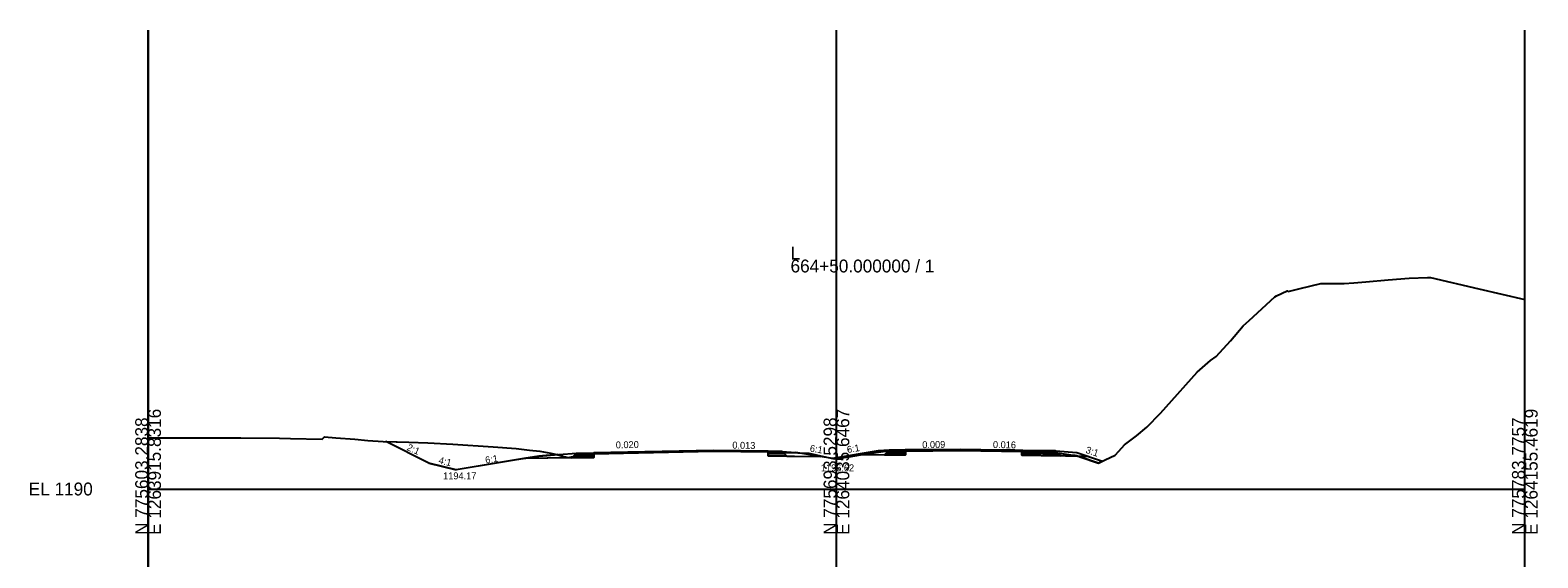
# Model space of a CAD drawing. Extents: x -41 to 1262860, y -100 to 777489.
# Drawn here: x -25.7 to 302.8, y 965 to 1080 of the extents above; entities that cross this region are included whole.
import ezdxf

# ---------------------------------------------------------------- set-up
doc = ezdxf.new("R2010")
doc.units = 0
for name, color, linetype in [('Exist Cross Section Cell', 7, 'Continuous'), ('Exist XS Center Line Elevation Label', 7, 'Continuous'), ('Exist XS Ground Line', 7, 'Continuous'), ('Prop CMT Pvmt Course 1', 7, 'Continuous'), ('Prop CMT Pvmt Surface', 7, 'Continuous'), ('Prop CMT Shld Paved Course 1', 7, 'Continuous'), ('Prop CMT Shld Paved Course 2', 7, 'Continuous'), ('Prop CMT Shld Paved Course 4', 7, 'Continuous'), ('Prop CMT Subgrade Earthwork', 7, 'Continuous'), ('Prop XS Ditch Standard Text', 7, 'Continuous'), ('Prop XS Earthwork Shape', 7, 'Continuous'), ('Prop XS Exc Vertical Line 1', 7, 'Continuous'), ('Prop XS Exc Vertical Line 2', 7, 'Continuous'), ('Prop XS Exc Vertical Line 3', 7, 'Continuous'), ('Prop XS Finish Grade', 7, 'Continuous'), ('Prop XS SE Text', 7, 'Continuous'), ('Prop XS Side Slope Text', 7, 'Continuous'), ('Scratch_Level_1', 7, 'Continuous'), ('Scratch_Level_4', 7, 'Continuous'), ('Scratch_Level_6', 7, 'Continuous')]:
    doc.layers.add(name, color=color, linetype=linetype)

msp = doc.modelspace()

# ---------------------------------------------------------------- linework, layer by layer
at = {"layer": 'Exist Cross Section Cell'}
for p, q in [((150, 980), (150, 1030)), ((0, 980), (150, 980)), ((150, 980), (300, 980))]:
    msp.add_line(p, q, dxfattribs=at)
at = {"layer": 'Exist XS Ground Line'}
msp.add_lwpolyline([(0, 991.14), (1.75, 991.12), (8.87, 991.17), (14.21, 991.19), (20.2, 991.13), (28.64, 991.05), (31.06, 991.01), (37.96, 990.84), (38.11, 990.98), (38.46, 991.34), (40.88, 991.13), (45.06, 990.85), (47.87, 990.6), (51.21, 990.34), (56.8, 990.19), (60.95, 990.1), (66.42, 989.81), (75.19, 989.22), (80.19, 988.85), (83.12, 988.48), (85.39, 988.22), (87.73, 987.78), (89.04, 987.54), (90.02, 987.26), (91.52, 986.86), (93.7, 987.31), (95.66, 987.7), (95.94, 987.71), (97.25, 987.75), (107.68, 988.02), (110.64, 988.08), (118.83, 988.24), (122.91, 988.32), (126.36, 988.25), (135.5, 988.07), (137.17, 988.01), (138.41, 987.96), (141.81, 987.89), (143.98, 987.79), (147.21, 987.09), (149.61, 986.57), (152.74, 987.04), (155.24, 987.46), (156.25, 987.59), (161.11, 988.29), (163.33, 988.37), (164.53, 988.42), (169.11, 988.48), (176.77, 988.59), (184.31, 988.54), (188.9, 988.53), (190.63, 988.48), (192.56, 988.41), (194.58, 988.26), (195.54, 988.2), (201.62, 987.41), (201.96, 987.37), (202.3, 987.27), (203.02, 987.02), (207.07, 985.67), (208.57, 986.33), (210.7, 987.35), (211.54, 988.28), (212.78, 989.61), (215.4, 991.6), (217.64, 993.47), (220.64, 996.51), (221.82, 997.89), (228.59, 1005.5), (231.49, 1007.99), (232.71, 1008.91), (235.86, 1012.29), (238.65, 1015.53), (239.94, 1016.71), (245.56, 1021.89), (245.89, 1022.1), (248.2, 1023.17), (248.43, 1023.02), (251.05, 1023.73), (255.56, 1024.77), (257.19, 1024.79), (260.66, 1024.78), (262.76, 1024.94), (265.35, 1025.15), (270.24, 1025.62), (274.8, 1025.93), (278.82, 1026.12), (279.46, 1026.07), (290, 1023.59), (300, 1021.33)], dxfattribs=at)
at = {"layer": 'Prop CMT Pvmt Course 1'}
msp.add_line((138.4, 987.96), (135.11, 988), dxfattribs=at)
for points in [[(97.15, 987.63), (97.15, 987.88), (97.15, 987.88), (123.11, 988.4), (135.11, 988.25), (135.11, 988), (123.11, 988.15), (97.15, 987.63), (97.15, 987.63), (97.15, 987.63)], [(190.37, 988.16), (190.37, 988.41), (177.01, 988.62), (177.01, 988.62), (177.01, 988.62), (165.06, 988.52), (165.06, 988.52), (165.06, 988.27), (177.01, 988.37), (177.01, 988.37), (177.01, 988.37), (190.37, 988.16)]]:
    msp.add_lwpolyline(points, dxfattribs=at)
at = {"layer": 'Prop CMT Pvmt Surface'}
for p, q in [((93.4, 987.83), (97.15, 987.88)), ((123.11, 988.4), (97.15, 987.88)), ((123.11, 988.4), (135.11, 988.25)), ((135.11, 988.25), (138.15, 988.21)), ((161.47, 988.49), (165.06, 988.52)), ((165.06, 988.52), (177.01, 988.62)), ((177.01, 988.62), (190.37, 988.41)), ((190.37, 988.41), (197.71, 988.3))]:
    msp.add_line(p, q, dxfattribs=at)
at = {"layer": 'Prop CMT Shld Paved Course 1'}
for p, q in [((93.14, 987.57), (93.4, 987.83)), ((97.15, 987.63), (93.14, 987.57)), ((93.14, 987.57), (93.14, 987.57)), ((93.14, 987.57), (93.14, 987.57)), ((93.4, 987.83), (93.4, 987.83)), ((97.15, 987.88), (97.15, 987.63)), ((97.15, 987.63), (97.15, 987.63)), ((138.15, 988.21), (135.11, 988.25)), ((138.4, 987.96), (138.15, 988.21))]:
    msp.add_line(p, q, dxfattribs=at)
for points in [[(165.06, 988.52), (161.47, 988.49), (161.47, 988.49), (161.23, 988.24), (165.06, 988.27), (165.06, 988.27), (165.06, 988.27), (165.06, 988.52), (165.01, 988.52)], [(197.71, 988.3), (190.37, 988.41), (190.37, 988.16), (190.37, 988.16), (194.62, 988.1), (194.62, 988.1), (197.96, 988.05), (197.71, 988.3), (194.37, 988.35)]]:
    msp.add_lwpolyline(points, dxfattribs=at)
at = {"layer": 'Prop CMT Shld Paved Course 2'}
for p, q in [((92.8, 987.23), (93.14, 987.57)), ((92.8, 987.23), (97.15, 987.3)), ((92.8, 987.23), (92.8, 987.23)), ((92.8, 987.23), (92.8, 987.23)), ((93.14, 987.57), (97.15, 987.63)), ((93.14, 987.57), (93.14, 987.57)), ((97.15, 987.63), (97.15, 987.3)), ((97.15, 987.29), (97.15, 987.29)), ((135.11, 987.66), (135.11, 988)), ((138.72, 987.62), (135.11, 987.66)), ((138.72, 987.62), (138.4, 987.96))]:
    msp.add_line(p, q, dxfattribs=at)
for points in [[(165.06, 988.27), (161.23, 988.24), (161.23, 988.24), (160.91, 987.9), (165.06, 987.94), (165.06, 987.94), (165.06, 987.94), (165.06, 988.27), (165.02, 988.27)], [(194.62, 988.1), (190.37, 988.16), (190.37, 987.83), (190.37, 987.83), (194.95, 987.76), (194.95, 987.76), (198.3, 987.71), (197.96, 988.05), (194.62, 988.1)]]:
    msp.add_lwpolyline(points, dxfattribs=at)
at = {"layer": 'Prop CMT Shld Paved Course 4'}
for p, q in [((92.34, 986.77), (92.8, 987.23)), ((92.34, 986.77), (97.15, 986.84)), ((92.34, 986.77), (92.34, 986.77)), ((92.34, 986.77), (92.34, 986.77)), ((92.8, 987.23), (92.8, 987.23)), ((92.8, 987.23), (92.8, 987.23)), ((97.15, 987.3), (97.15, 986.84)), ((97.15, 986.83), (97.15, 986.83)), ((135.11, 987.21), (135.11, 987.66)), ((139.17, 987.16), (135.11, 987.21)), ((139.17, 987.16), (138.72, 987.62))]:
    msp.add_line(p, q, dxfattribs=at)
for points in [[(165.06, 987.94), (160.91, 987.9), (160.91, 987.9), (160.91, 987.9), (160.91, 987.9), (160.47, 987.44), (165.06, 987.48), (165.06, 987.48), (165.06, 987.48), (165.06, 987.94), (165.02, 987.94)], [(194.95, 987.76), (190.37, 987.83), (190.37, 987.37), (190.37, 987.37), (198.77, 987.24), (198.77, 987.24), (198.3, 987.71), (198.3, 987.71), (195.45, 987.75), (194.95, 987.76), (194.95, 987.76)]]:
    msp.add_lwpolyline(points, dxfattribs=at)
at = {"layer": 'Prop CMT Subgrade Earthwork'}
for p, q in [((97.15, 986.84), (81.88, 986.62)), ((97.15, 986.84), (97.15, 987.75)), ((135.11, 988.08), (135.11, 987.21)), ((135.11, 987.21), (146.57, 987.06)), ((165.06, 987.48), (153.6, 987.39)), ((165.06, 987.48), (165.06, 988.43)), ((190.37, 987.37), (190.37, 988.49)), ((190.37, 987.37), (204.7, 987.15))]:
    msp.add_line(p, q, dxfattribs=at)
at = {"layer": 'Prop XS Earthwork Shape'}
for points in [[(81.88, 986.62), (67.15, 984.17), (61.15, 985.67), (51.84, 990.32), (56.8, 990.19), (60.95, 990.1), (66.42, 989.81), (75.19, 989.22), (80.19, 988.85), (83.12, 988.48), (85.39, 988.22), (87.73, 987.78), (89.04, 987.54), (89.2, 987.49), (85.15, 987.17)], [(89.2, 987.49), (90.02, 987.26), (91.52, 986.86), (92.67, 987.1), (92.34, 986.77), (81.88, 986.62), (85.15, 987.17)], [(92.67, 987.1), (92.34, 986.77), (97.15, 986.84), (97.15, 987.75), (95.94, 987.71), (95.66, 987.7), (93.7, 987.31)], [(138.39, 987.96), (139.17, 987.16), (135.11, 987.21), (135.11, 988.08), (135.5, 988.07), (137.17, 988.01)], [(138.39, 987.96), (139.17, 987.16), (146.57, 987.06), (141.56, 987.9), (138.41, 987.96)], [(141.56, 987.9), (141.81, 987.89), (143.98, 987.79), (147.21, 987.09), (149.21, 986.65), (149.11, 986.64), (146.57, 987.06)], [(153.6, 987.39), (149.21, 986.65), (149.61, 986.57), (152.74, 987.04), (154.84, 987.4)], [(160.47, 987.44), (154.84, 987.4), (155.24, 987.46), (156.25, 987.59), (161.11, 988.29), (161.28, 988.29)], [(161.28, 988.29), (163.33, 988.37), (164.53, 988.42), (165.06, 988.43), (165.06, 987.48), (160.47, 987.44)], [(198.15, 987.86), (198.77, 987.24), (190.37, 987.37), (190.37, 988.49), (190.63, 988.48), (192.56, 988.41), (194.58, 988.26), (195.54, 988.2)], [(198.15, 987.86), (201.62, 987.41), (201.96, 987.37), (202.3, 987.27), (202.54, 987.18), (198.77, 987.24)], [(202.54, 987.18), (204.7, 987.15), (207.97, 986.06), (207.07, 985.67), (203.02, 987.02)]]:
    msp.add_lwpolyline(points, close=True, dxfattribs=at)
at = {"layer": 'Prop XS Exc Vertical Line 1'}
msp.add_line((0, 880), (0, 1080), dxfattribs=at)
at = {"layer": 'Prop XS Exc Vertical Line 2'}
msp.add_line((150, 880), (150, 1080), dxfattribs=at)
at = {"layer": 'Prop XS Exc Vertical Line 3'}
msp.add_line((300, 880), (300, 1080), dxfattribs=at)
at = {"layer": 'Prop XS Finish Grade'}
for p, q in [((61.15, 985.67), (51.84, 990.32)), ((93.4, 987.83), (92.34, 986.77)), ((138.15, 988.21), (139.17, 987.16)), ((149.11, 986.64), (141.1, 987.97)), ((141.11, 987.9), (141.11, 987.9)), ((159.06, 988.3), (149.11, 986.64)), ((161.47, 988.49), (160.47, 987.44)), ((197.71, 988.3), (202.37, 987.93)), ((197.71, 988.3), (198.77, 987.24)), ((202.37, 987.93), (207.97, 986.06))]:
    msp.add_line(p, q, dxfattribs=at)
for points in [[(61.15, 985.67), (61.15, 985.67), (67.15, 984.17)], [(85.15, 987.17), (67.15, 984.17)], [(85.15, 987.17), (89.4, 987.51), (93.4, 987.83)], [(138.15, 988.21), (141.1, 987.97)], [(161.47, 988.49), (159.06, 988.3)]]:
    msp.add_lwpolyline(points, dxfattribs=at)
at = {"layer": 'Scratch_Level_1'}
msp.add_line((135.11, 988.25), (123.11, 988.4), dxfattribs=at)
at = {"layer": 'Scratch_Level_4'}
msp.add_line((300, 880), (300, 1080), dxfattribs=at)
at = {"layer": 'Scratch_Level_6'}
msp.add_line((0, 1080), (0, 880), dxfattribs=at)

# ---------------------------------------------------------------- texts
at = {"layer": 'Exist Cross Section Cell'}
for s, p in [('L', (140, 1030)), ('664+50.000000 / 1', (140, 1027.2)), ('EL 1190', (-26, 978.6))]:
    msp.add_text(s, height=2.8, dxfattribs=at).set_placement(p)
for s, p in [('E 1263915.8316', (2.8, 970)), ('E 1264035.6467', (152.8, 970)), ('E 1264155.4619', (302.8, 970)), ('N 775603.2838', (0, 970)), ('N 775693.5298', (150, 970)), ('N 775783.7757', (300, 970))]:
    msp.add_text(s, height=2.8, rotation=90, dxfattribs=at).set_placement(p)
at = {"layer": 'Exist XS Center Line Elevation Label'}
msp.add_text('1196.62', height=1.5, dxfattribs=at).set_placement((146.61, 983.87))
at = {"layer": 'Prop XS Ditch Standard Text'}
msp.add_text('1194.17', height=1.5, dxfattribs=at).set_placement((64.29, 982.12))
at = {"layer": 'Prop XS SE Text'}
for s, rotation, p in [('0.020', 1.1458, (101.93, 988.86)), ('0.013', 359.002, (127.3, 988.82)), ('0.009', 0.7647, (168.71, 988.91)), ('0.016', 358.8542, (184.09, 988.95))]:
    msp.add_text(s, height=1.5, rotation=rotation, dxfattribs=at).set_placement(p)
at = {"layer": 'Prop XS Side Slope Text'}
for s, rotation, p in [('2:1', 335.8411, (56.25, 988.54)), ('6:1', 350.5377, (144.12, 988.19)), ('6:1', 9.4623, (152.41, 987.83)), ('3:1', 341.5651, (204.19, 987.91)), ('4:1', 345.9638, (63.2, 985.61)), ('6:1', 9.4623, (73.6, 985.54))]:
    msp.add_text(s, height=1.5, rotation=rotation, dxfattribs=at).set_placement(p)

doc.saveas('drawing.dxf')
